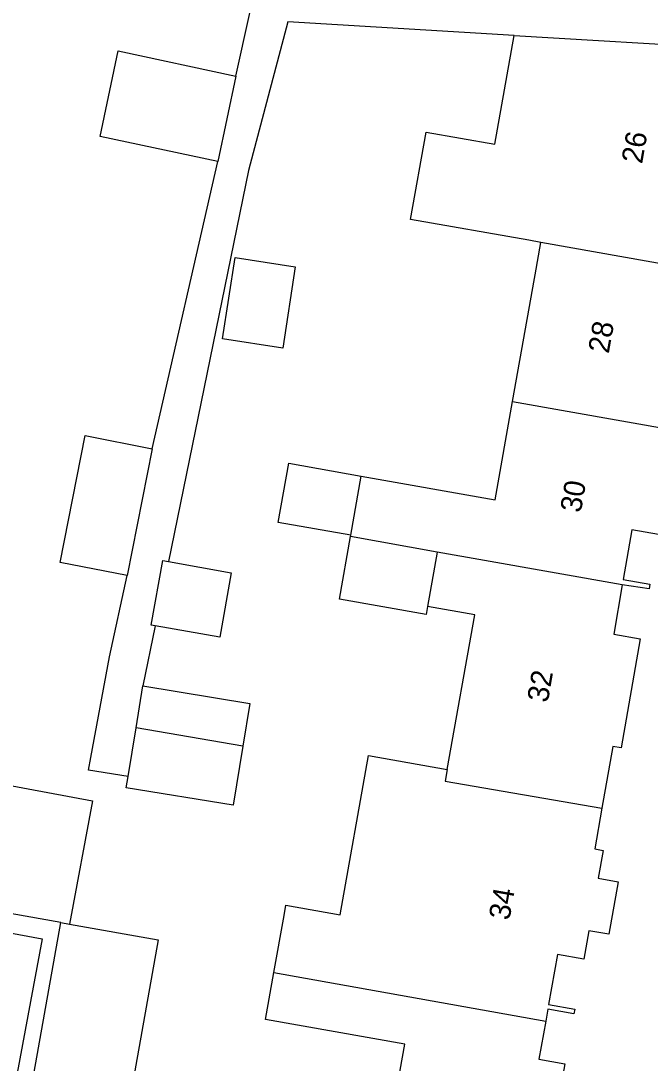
# Model space of a CAD drawing. Extents: x 163686 to 164493, y 382719 to 383870.
# Drawn here: x 164008.1 to 164037.9, y 383405.27 to 383454.64 of the extents above; entities that cross this region are included whole.
import ezdxf

# ---------------------------------------------------------------- set-up
doc = ezdxf.new("R2010")
doc.units = 0
for name, color, linetype in [('IMGEO_Pand', 7, 'Continuous'), ('IMGEO_Pand_nummerreeks', 7, 'Continuous'), ('IMGEO_Voetpad_open', 7, 'Continuous')]:
    doc.layers.add(name, color=color, linetype=linetype)

msp = doc.modelspace()

# ---------------------------------------------------------------- linework, layer by layer
at = {"layer": 'IMGEO_Pand'}
for points in [[(164032.722, 383444.147), (164032.16, 383444.247), (164026.552, 383445.224), (164027.291, 383449.371), (164030.539, 383448.792), (164031.458, 383453.951)], [(164031.458, 383453.951), (164041.575, 383453.353)], [(164017.423, 383447.979), (164011.852, 383449.17), (164012.717, 383453.216), (164018.288, 383452.025)], [(164018.288, 383452.025), (164017.423, 383447.979)], [(164031.386, 383436.615), (164032.42, 383442.444), (164032.45, 383442.614), (164032.722, 383444.147)], [(164039.226, 383442.989), (164032.722, 383444.147)], [(164018.251, 383443.435), (164021.093, 383442.997), (164020.5, 383439.14), (164017.658, 383439.578), (164018.251, 383443.435)], [(164024.223, 383433.078), (164030.559, 383431.954), (164031.386, 383436.615)], [(164031.386, 383436.615), (164039.151, 383435.233)], [(164013.129, 383428.366), (164009.966, 383428.99), (164011.152, 383434.999), (164014.315, 383434.374)], [(164039.151, 383435.233), (164038.295, 383430.317), (164037.036, 383430.536), (164036.625, 383428.175), (164037.882, 383427.956), (164037.844, 383427.739), (164036.579, 383427.919)], [(164014.315, 383434.374), (164013.129, 383428.366)], [(164023.727, 383430.276), (164020.289, 383430.886), (164020.786, 383433.688), (164024.223, 383433.078)], [(164023.727, 383430.276), (164024.223, 383433.078)], [(164027.361, 383426.894), (164027.295, 383426.52), (164023.189, 383427.248), (164023.715, 383430.21)], [(164023.715, 383430.21), (164023.727, 383430.276)], [(164027.82, 383429.479), (164023.715, 383430.21)], [(164014.465, 383425.984), (164014.279, 383426.017), (164014.821, 383429.073), (164015.088, 383429.026)], [(164027.82, 383429.479), (164027.361, 383426.894)], [(164036.579, 383427.919), (164030.05, 383429.082), (164027.82, 383429.479)], [(164015.088, 383429.026), (164018.068, 383428.497), (164017.526, 383425.442), (164014.465, 383425.984)], [(164036.579, 383427.919), (164036.173, 383425.588), (164037.43, 383425.368), (164036.53, 383420.206), (164036.137, 383420.276), (164035.615, 383417.342)], [(164028.293, 383419.172), (164029.592, 383426.498), (164027.361, 383426.894)], [(164013.557, 383421.16), (164013.881, 383423.135)], [(164013.881, 383423.135), (164018.947, 383422.303), (164018.616, 383420.284)], [(164013.177, 383418.843), (164013.557, 383421.16)], [(164018.616, 383420.284), (164013.557, 383421.16)], [(164018.616, 383420.284), (164018.156, 383417.482), (164013.09, 383418.313), (164013.177, 383418.843)], [(164020.083, 383409.556), (164020.565, 383412.263), (164020.653, 383412.755), (164023.223, 383412.297), (164024.564, 383419.835), (164028.293, 383419.172)], [(164028.293, 383419.172), (164028.196, 383418.626), (164035.615, 383417.342)], [(164009.99, 383411.932), (164004.036, 383412.992), (164005.13, 383418.879), (164011.497, 383417.696), (164010.412, 383411.857)], [(164035.615, 383417.342), (164035.273, 383415.42), (164035.666, 383415.35), (164035.432, 383414.031), (164036.377, 383413.863), (164035.934, 383411.372), (164034.989, 383411.54), (164034.75, 383410.194), (164033.508, 383410.414), (164033.086, 383408.048), (164034.328, 383407.827), (164034.29, 383407.609), (164033.056, 383407.828), (164032.956, 383407.264)], [(164009.118, 383411.151), (164007.636, 383403.177), (164003.615, 383403.925), (164005.097, 383411.898), (164009.118, 383411.151)], [(164010.412, 383411.857), (164014.598, 383411.112), (164013.258, 383403.58), (164008.65, 383404.4), (164009.99, 383411.932)], [(164009.99, 383411.932), (164010.412, 383411.857)], [(164032.956, 383407.264), (164032.634, 383405.452), (164033.865, 383405.233), (164032.949, 383400.077), (164025.433, 383401.414), (164026.279, 383406.167), (164019.689, 383407.34), (164020.083, 383409.556)], [(164020.083, 383409.556), (164032.956, 383407.264)]]:
    msp.add_lwpolyline(points, dxfattribs=at)
at = {"layer": 'IMGEO_Voetpad_open'}
for points in [[(164018.288, 383452.025), (164022.253, 383469.996)], [(164031.458, 383453.951), (164020.739, 383454.592), (164018.884, 383447.55), (164015.088, 383429.026)], [(164014.315, 383434.374), (164017.423, 383447.979)], [(164013.177, 383418.843), (164011.3, 383419.151), (164011.411, 383419.743), (164012.299, 383424.51), (164013.129, 383428.366)], [(164014.465, 383425.984), (164013.881, 383423.135)]]:
    msp.add_lwpolyline(points, dxfattribs=at)

# ---------------------------------------------------------------- texts
at = {"layer": 'IMGEO_Pand_nummerreeks'}
for s, rotation, p in [('26', 80.0938, (164037.515, 383447.838)), ('28', 79.962, (164035.935, 383438.851)), ('30', 80.1224, (164034.613, 383431.308)), ('32', 80.1568, (164033.05, 383422.317)), ('34', 79.8875, (164031.232, 383412.006))]:
    msp.add_text(s, height=1, rotation=rotation, dxfattribs=at).set_placement(p)

doc.saveas('drawing.dxf')
